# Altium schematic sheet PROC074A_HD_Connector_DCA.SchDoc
size 431 x 279 mm; Date: Not shown in title block; ApprovedBy: Not shown in title block; CheckedBy: Not shown in title block; Author: Not shown in title block; CompanyName: Not shown in title block; Engineer: Not shown in title block; Organization: Not shown in title block; Address1: Not shown in title block; Address2: Not shown in title block; Address3: Not shown in title block; Address4: Not shown in title block; DocumentNumber: 1; Revision: Use project parameter SCH_Rev; SheetNumber: 21; SheetTotal: 22; PageSetup: Record=PageOptions¦CenterHorizontal=True¦CenterVertical=True¦PrintScale=1.00¦XCorrection=1.00¦YCorrection=1.00¦PrintKind=0¦BorderSize=5000000¦LeftOffset=0¦BottomOffset=0¦Orientation=2¦PaperLength=1000¦PaperWidth=1000¦Scale=100¦PaperSource=15¦PrintQuality=600¦MediaType=1¦DitherType=10¦PaperKind=Letter¦PrintScaleMode=1
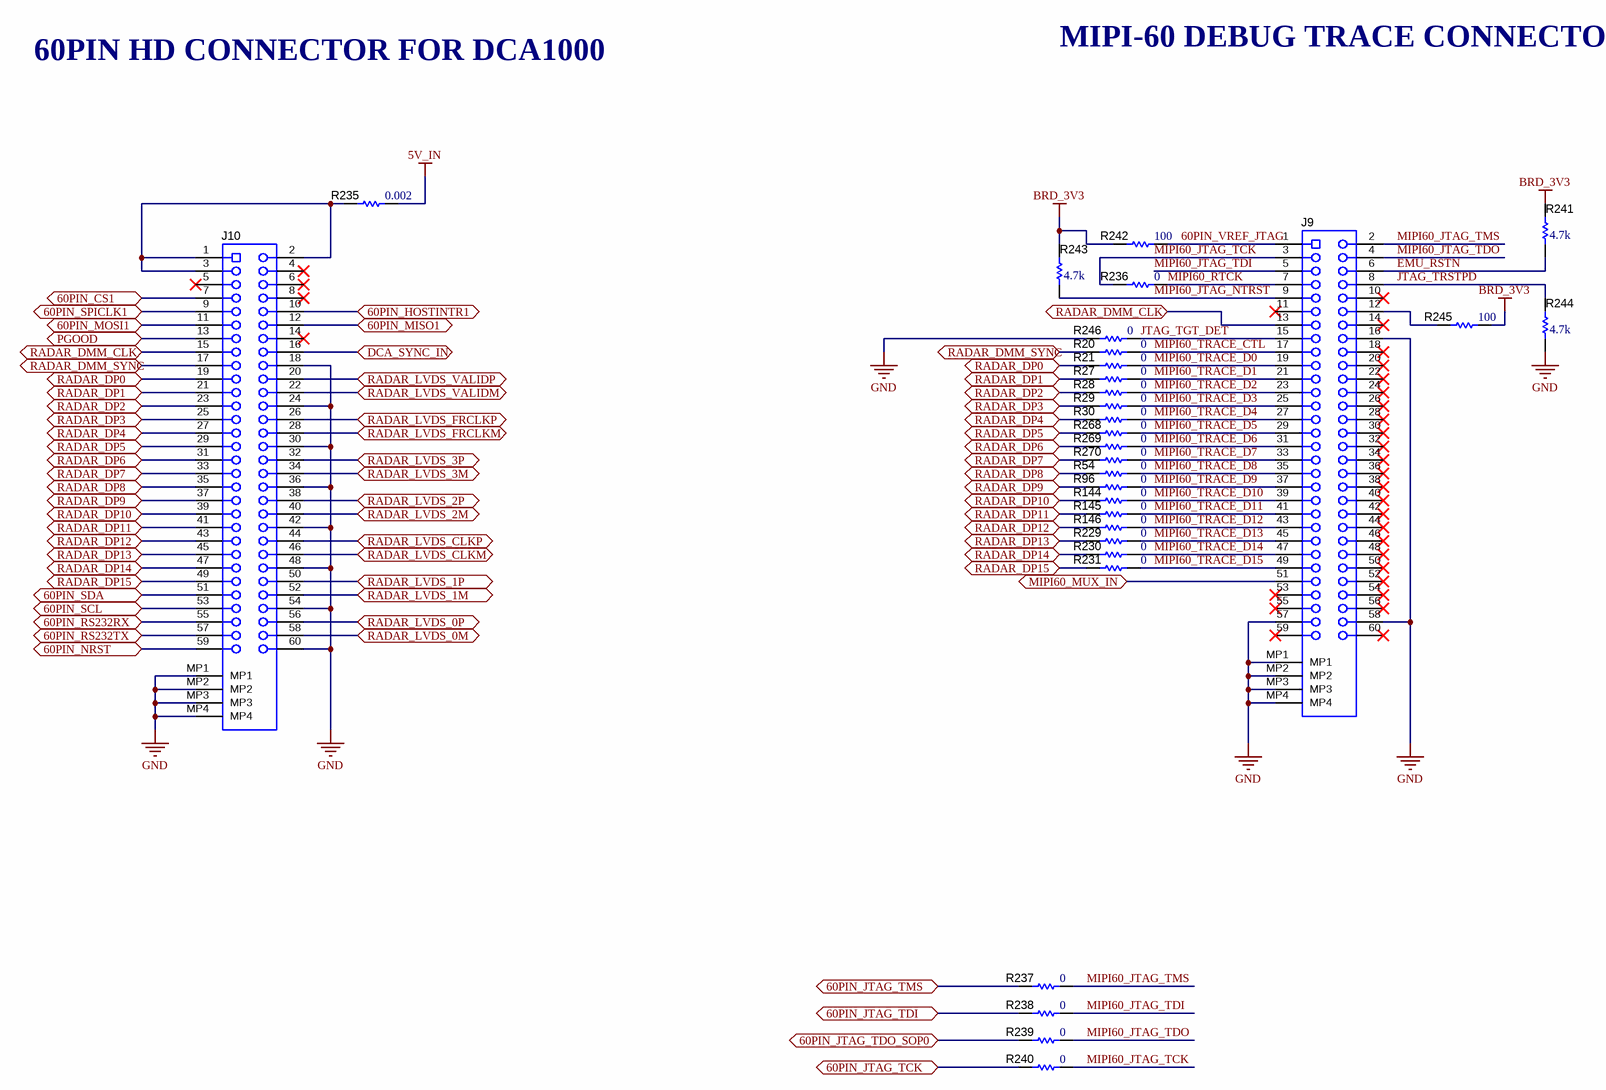
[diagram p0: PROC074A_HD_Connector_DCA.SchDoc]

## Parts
J9  QSH-030-01-L-D-A  [Samtec_QSH-030-01-X-D-A]  (value not drawn)
J10  QSH-030-01-L-D-A  [Samtec_QSH-030-01-X-D-A]  (value not drawn)
R20  ValueDisplayed: 0  [0402]  (hidden comment: ERJ-2GE0R00X)
R21  ValueDisplayed: 0  [0402]  (hidden comment: ERJ-2GE0R00X)
R27  ValueDisplayed: 0  [0402]  (hidden comment: ERJ-2GE0R00X)
R28  ValueDisplayed: 0  [0402]  (hidden comment: ERJ-2GE0R00X)
R29  ValueDisplayed: 0  [0402]  (hidden comment: ERJ-2GE0R00X)
R30  ValueDisplayed: 0  [0402]  (hidden comment: ERJ-2GE0R00X)
R54  ValueDisplayed: 0  [0402]  (hidden comment: ERJ-2GE0R00X)
R96  ValueDisplayed: 0  [0402]  (hidden comment: ERJ-2GE0R00X)
R144  ValueDisplayed: 0  [0402]  (hidden comment: ERJ-2GE0R00X)
R145  ValueDisplayed: 0  [0402]  (hidden comment: ERJ-2GE0R00X)
R146  ValueDisplayed: 0  [0402]  (hidden comment: ERJ-2GE0R00X)
R229  ValueDisplayed: 0  [0402]  (hidden comment: ERJ-2GE0R00X)
R230  ValueDisplayed: 0  [0402]  (hidden comment: ERJ-2GE0R00X)
R231  ValueDisplayed: 0  [0402]  (hidden comment: ERJ-2GE0R00X)
R235  ValueDisplayed: 0.002  [1206]  (hidden comment: PMR18EZPFV2L00)
R236  ValueDisplayed: 0  [0402]  (hidden comment: ERJ-2GE0R00X)
R237  ValueDisplayed: 0  [0402]  (hidden comment: ERJ-2GE0R00X)
R238  ValueDisplayed: 0  [0402]  (hidden comment: ERJ-2GE0R00X)
R239  ValueDisplayed: 0  [0402]  (hidden comment: ERJ-2GE0R00X)
R240  ValueDisplayed: 0  [0402]  (hidden comment: ERJ-2GE0R00X)
R241  ValueDisplayed: 4.7k  [0402]  (hidden comment: CRCW04024K70JNED)
R242  ValueDisplayed: 100  [0402]  (hidden comment: ERJ-2GEJ101X)
R243  ValueDisplayed: 4.7k  [0402]  (hidden comment: CRCW04024K70JNED)
R244  ValueDisplayed: 4.7k  [0402]  (hidden comment: CRCW04024K70JNED)
R245  ValueDisplayed: 100  [0402]  (hidden comment: ERJ-2GEJ101X)
R246  ValueDisplayed: 0  [0402]  (hidden comment: ERJ-2GE0R00X)
R268  ValueDisplayed: 0  [0402]  (hidden comment: ERJ-2GE0R00X)
R269  ValueDisplayed: 0  [0402]  (hidden comment: ERJ-2GE0R00X)
R270  ValueDisplayed: 0  [0402]  (hidden comment: ERJ-2GE0R00X)

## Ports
60PIN_CS1, 60PIN_HOSTINTR1, 60PIN_JTAG_TCK, 60PIN_JTAG_TDI, 60PIN_JTAG_TDO_SOP0, 60PIN_JTAG_TMS, 60PIN_MISO1, 60PIN_MOSI1, 60PIN_NRST, 60PIN_RS232RX, 60PIN_RS232TX, 60PIN_SCL, 60PIN_SDA, 60PIN_SPICLK1, DCA_SYNC_IN, MIPI60_MUX_IN, PGOOD, RADAR_DMM_CLK, RADAR_DMM_SYNC, RADAR_DP0, RADAR_DP1, RADAR_DP2, RADAR_DP3, RADAR_DP4, RADAR_DP5, RADAR_DP6, RADAR_DP7, RADAR_DP8, RADAR_DP9, RADAR_DP10, RADAR_DP11, RADAR_DP12, RADAR_DP13, RADAR_DP14, RADAR_DP15, RADAR_LVDS_0M, RADAR_LVDS_0P, RADAR_LVDS_1M, RADAR_LVDS_1P, RADAR_LVDS_2M, RADAR_LVDS_2P, RADAR_LVDS_3M, RADAR_LVDS_3P, RADAR_LVDS_CLKM, RADAR_LVDS_CLKP, RADAR_LVDS_FRCLKM, RADAR_LVDS_FRCLKP, RADAR_LVDS_VALIDM, RADAR_LVDS_VALIDP

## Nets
5V_IN: R235.2
BRD_3V3: R241.2 R242.2 R243.2 R245.1
GND: J9.16 J9.57 J9.58 J9.MP1 J9.MP2 J9.MP3 J9.MP4 J10.18 J10.24 J10.30 J10.36 J10.42 J10.48 J10.54 J10.60 J10.MP1 J10.MP2 J10.MP3 J10.MP4 R244.1 R246.1
60PIN_CS1: J10.7 ; port 60PIN_CS1
60PIN_HOSTINTR1: J10.10 ; port 60PIN_HOSTINTR1
60PIN_JTAG_TCK: R240.1 ; port 60PIN_JTAG_TCK
60PIN_JTAG_TDI: R238.1 ; port 60PIN_JTAG_TDI
60PIN_JTAG_TDO_SOP0: R239.1 ; port 60PIN_JTAG_TDO_SOP0
60PIN_JTAG_TMS: R237.1 ; port 60PIN_JTAG_TMS
60PIN_MISO1: J10.12 ; port 60PIN_MISO1
60PIN_MOSI1: J10.11 ; port 60PIN_MOSI1
60PIN_NRST: J10.59 ; port 60PIN_NRST
60PIN_RS232RX: J10.55 ; port 60PIN_RS232RX
60PIN_RS232TX: J10.57 ; port 60PIN_RS232TX
60PIN_SCL: J10.53 ; port 60PIN_SCL
60PIN_SDA: J10.51 ; port 60PIN_SDA
60PIN_SPICLK1: J10.9 ; port 60PIN_SPICLK1
60PIN_VREF_JTAG: J9.1 R242.1
DCA_SYNC_IN: J10.16 ; port DCA_SYNC_IN
EMU_RSTN: J9.6 R241.1
JTAG_TGT_DET: J9.15 R246.2
JTAG_TRSTPD: J9.8 R244.2
MIPI60_JTAG_NTRST: J9.9 R243.1
MIPI60_JTAG_TCK: J9.3 R236.1 R240.2
MIPI60_JTAG_TDI: J9.5 R238.2
MIPI60_JTAG_TDO: J9.4 R239.2
MIPI60_JTAG_TMS: J9.2 R237.2
MIPI60_MUX_IN: J9.51 ; port MIPI60_MUX_IN
MIPI60_RTCK: J9.7 R236.2
MIPI60_TRACE_CTL: J9.17 R20.2
MIPI60_TRACE_D0: J9.19 R21.2
MIPI60_TRACE_D1: J9.21 R27.2
MIPI60_TRACE_D2: J9.23 R28.2
MIPI60_TRACE_D3: J9.25 R29.2
MIPI60_TRACE_D4: J9.27 R30.2
MIPI60_TRACE_D5: J9.29 R268.2
MIPI60_TRACE_D6: J9.31 R269.2
MIPI60_TRACE_D7: J9.33 R270.2
MIPI60_TRACE_D8: J9.35 R54.2
MIPI60_TRACE_D9: J9.37 R96.2
MIPI60_TRACE_D10: J9.39 R144.2
MIPI60_TRACE_D11: J9.41 R145.2
MIPI60_TRACE_D12: J9.43 R146.2
MIPI60_TRACE_D13: J9.45 R229.2
MIPI60_TRACE_D14: J9.47 R230.2
MIPI60_TRACE_D15: J9.49 R231.2
PGOOD: J10.13 ; port PGOOD
RADAR_DMM_CLK: J9.13 J10.15 ; port RADAR_DMM_CLK
RADAR_DMM_SYNC: J10.17 R20.1 ; port RADAR_DMM_SYNC
RADAR_DP0: J10.19 R21.1 ; port RADAR_DP0
RADAR_DP1: J10.21 R27.1 ; port RADAR_DP1
RADAR_DP2: J10.23 R28.1 ; port RADAR_DP2
RADAR_DP3: J10.25 R29.1 ; port RADAR_DP3
RADAR_DP4: J10.27 R30.1 ; port RADAR_DP4
RADAR_DP5: J10.29 R268.1 ; port RADAR_DP5
RADAR_DP6: J10.31 R269.1 ; port RADAR_DP6
RADAR_DP7: J10.33 R270.1 ; port RADAR_DP7
RADAR_DP8: J10.35 R54.1 ; port RADAR_DP8
RADAR_DP9: J10.37 R96.1 ; port RADAR_DP9
RADAR_DP10: J10.39 R144.1 ; port RADAR_DP10
RADAR_DP11: J10.41 R145.1 ; port RADAR_DP11
RADAR_DP12: J10.43 R146.1 ; port RADAR_DP12
RADAR_DP13: J10.45 R229.1 ; port RADAR_DP13
RADAR_DP14: J10.47 R230.1 ; port RADAR_DP14
RADAR_DP15: J10.49 R231.1 ; port RADAR_DP15
RADAR_LVDS_0M: J10.58 ; port RADAR_LVDS_0M
RADAR_LVDS_0P: J10.56 ; port RADAR_LVDS_0P
RADAR_LVDS_1M: J10.52 ; port RADAR_LVDS_1M
RADAR_LVDS_1P: J10.50 ; port RADAR_LVDS_1P
RADAR_LVDS_2M: J10.40 ; port RADAR_LVDS_2M
RADAR_LVDS_2P: J10.38 ; port RADAR_LVDS_2P
RADAR_LVDS_3M: J10.34 ; port RADAR_LVDS_3M
RADAR_LVDS_3P: J10.32 ; port RADAR_LVDS_3P
RADAR_LVDS_CLKM: J10.46 ; port RADAR_LVDS_CLKM
RADAR_LVDS_CLKP: J10.44 ; port RADAR_LVDS_CLKP
RADAR_LVDS_FRCLKM: J10.28 ; port RADAR_LVDS_FRCLKM
RADAR_LVDS_FRCLKP: J10.26 ; port RADAR_LVDS_FRCLKP
RADAR_LVDS_VALIDM: J10.22 ; port RADAR_LVDS_VALIDM
RADAR_LVDS_VALIDP: J10.20 ; port RADAR_LVDS_VALIDP
NetJ9_12: J9.12 R245.2
NetJ10_1: J10.1 J10.2 J10.3 R235.1

Not connected (* = marked no-connect by the designer): J9 10* 11* 14* 18* 20* 22* 24* 26* 28* 30* 32* 34* 36* 38* 40* 42* 44* 46* 48* 50* 52* 53* 54* 55* 56* 59* 60*; J10 4* 5* 6* 8* 14*

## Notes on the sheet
- 60PIN HD CONNECTOR FOR DCA1000
- MIPI-60 DEBUG TRACE CONNECTOR

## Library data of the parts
J9 J10 = CMP-0075524-1: Receptacle, 0.5 mm, 30x2, Gold, TH; Manufacturer: Samtec; Pitch_mm: 0.5; Gender: Female; Green_REACh: Passed; CT: False; Shrouded: N; RowSpacing_mm: 5.73; Green_Lifecycle: Active; Row_Count: 2
R20 R21 R27-R30 R54 R96 R144-R146 R229-R231 R236-R240 R246 R268-R270 = CMP-0026992-3: RES, 0, 5%, 0.1 W, AEC-Q200 Grade 0, 0402; Manufacturer: Panasonic; Power_W: 100mW; TempCo: 600 ppm/C; Value_Code: 0000; Value: 0; EIA_Code: E24; SizeX_mm: 1; SizeY_mm: 0.5; SizeZ_mm: 0.6; Value2: 0.1W; AEC Qualified: Y; VDC_V: 50V; AEC Category: Q200; SizeAreaWB_mm2: 3
R235 = CMP-0081623-1: RES, 0.002, 1%, 1 W, AEC-Q200 Grade 0, 1206; Manufacturer: Rohm; Value_Code: 2L000; SizeAreaWB_mm2: 10.92; SizeArea_mm2: 5.12; AEC Qualified: Y; AEC Category: Q200; Res_ohm: 2m; Value: 0.002; SizeZ_mm: 1.35; Green_REACh: Incomplete; TempCo: 100 ppm/C; AEC Grade: 0; Power_W: 1W; SizeY_mm: 1.6; Green_Lifecycle: Active; SizeX_mm: 3.2
R241 R243 R244 = CMP-0026938-5: RES, 4.7 k, 5%, 0.063 W, AEC-Q200 Grade 0, 0402; Manufacturer: Vishay-Dale; Power_W: 63mW; TempCo: 200 ppm/C; Value_Code: 4k70; Value: 4.7k; EIA_Code: E24; SizeX_mm: 1; SizeY_mm: 0.5; SizeZ_mm: 0.6; Value2: 0.063W; AEC Qualified: Y; VDC_V: 50V; AEC Category: Q200; AEC Grade: 0
R242 R245 = CMP-0026993-2: RES, 100, 5%, 0.1 W, AEC-Q200 Grade 0, 0402; Manufacturer: Panasonic; Power_W: 100mW; TempCo: 200 ppm/C; Value_Code: 100R; U/M: EA; Value: 100; EIA_Code: E24; SizeX_mm: 1; SizeY_mm: 0.5; SizeZ_mm: 0.6; Value2: 0.1W; AEC Qualified: Y; AEC Grade: 0; AEC Category: Q200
